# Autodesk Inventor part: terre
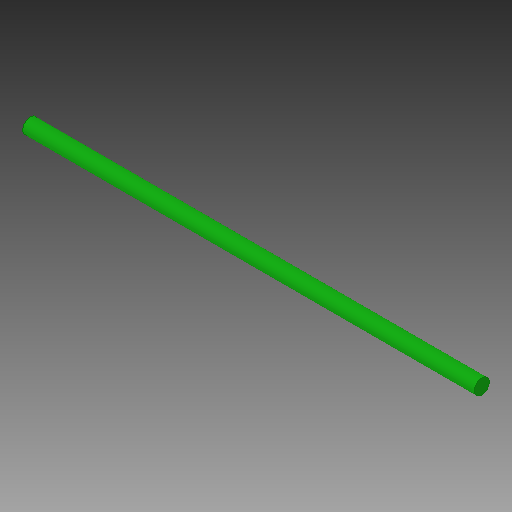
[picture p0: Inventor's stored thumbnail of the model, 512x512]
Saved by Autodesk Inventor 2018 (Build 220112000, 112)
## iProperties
Created: 2017-03
Part Number: terre
Material: Generic
Document SubType Name: Modeling
Designer: thierry.jost
Density: 1 g/cm^3
Appearance: Lisse - Rouge
Author: thierry.jost
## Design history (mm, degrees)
sketch "Sketch1"
  geometry: C1 r 2.5 at (0, 0); 1 further point
  constraints: 1 centre point, 1 coincident
  dimensions: "d0" = 5 diameter of C1
extrude "Extrusion1" new body sketch "Sketch1" distance "d1" = 150; taper "d2" = 0 deg
body "Solid1"
